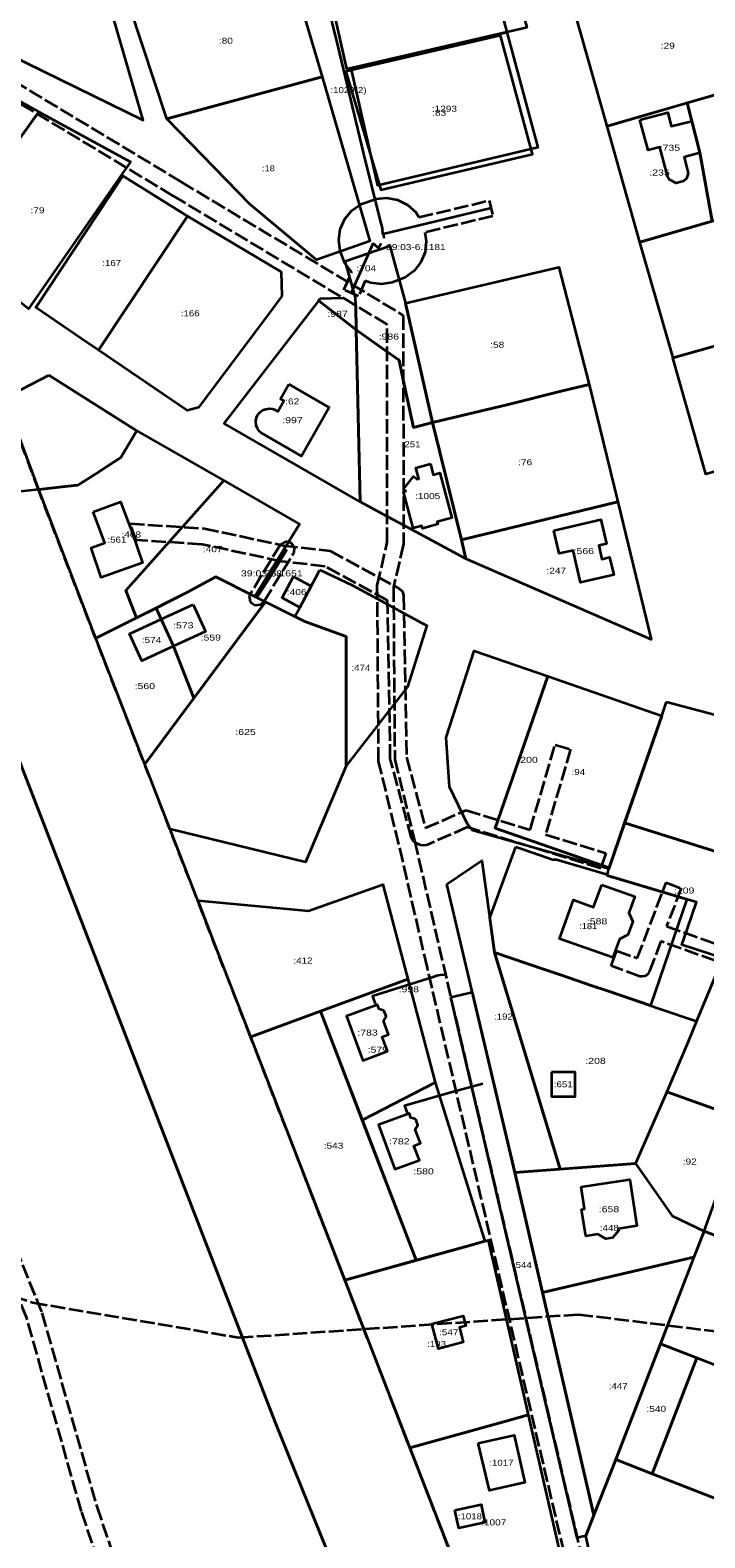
# Model space of a CAD drawing. Extents: x 1185507 to 1197690, y 352608 to 375774.
# Drawn here: x 1190232 to 1190399.7, y 364414.2 to 364788.9 of the extents above; entities that cross this region are included whole.
import ezdxf
from ezdxf.enums import TextEntityAlignment as Align

# ---------------------------------------------------------------- set-up
doc = ezdxf.new("R2010")
doc.units = 0
doc.header["$LTSCALE"] = 0.6
doc.linetypes.add('DOT_DASHED', pattern=[7.7, 5, -1.2, 0.3, -1.2])
doc.linetypes.add('LONG_DASHED', pattern=[7.5, 6, -1.5])
for name, color, linetype, lineweight in [('2', 7, 'Continuous', 35), ('4', 7, 'Continuous', 35), ('5', 7, 'DOT_DASHED', 35), ('7', 7, 'LONG_DASHED', 35), ('8', 7, 'Continuous', 35)]:
    doc.layers.add(name, color=color, linetype=linetype, lineweight=lineweight)

msp = doc.modelspace()

# ---------------------------------------------------------------- linework, layer by layer
at = {"layer": '2'}
for points in [[(1190203.76, 365183.45), (1190165.44, 365181.03), (1190143.28, 365179.63), (1190095.67, 365141.92), (1190101.13, 365121.7), (1190114.6, 365071.55), (1190134.43, 364996.3), (1190136.36, 364989.15), (1190143.36, 364963.22), (1190173.89, 364850.01), (1190182.86, 364818.75), (1190190.18, 364794.36), (1190194.07, 364783.25), (1190222.57, 364784.85), (1190260.08, 364766.56), (1190184.45, 365026.35), (1190319.42, 365061.39), (1190227.38, 365157.88), (1190211.55, 365175.02)], [(1190304.34, 364807.4), (1190340.66, 364817.71), (1190342.5, 364818.23), (1190346.35, 364819.32), (1190347.32, 364819.6), (1190355.39, 364789.56), (1190354.06, 364789.26), (1190350.41, 364788.44), (1190311.72, 364779.48), (1190310.66, 364779.27)], [(1190304.34, 364807.4), (1190340.66, 364817.71), (1190342.5, 364818.23), (1190350.41, 364788.44), (1190311.72, 364779.48), (1190310.66, 364779.27)], [(1190265.97, 364766.88), (1190256.67, 364795), (1190296.17, 364805.67), (1190304.54, 364777.29)], [(1190375.34, 364765.08), (1190367.16, 364793.94), (1190405.58, 364805.04), (1190413.76, 364776.18)], [(1190348.84, 364787.56), (1190310.41, 364778.62), (1190319.08, 364749.21), (1190356.85, 364758.13)], [(1190311.72, 364779.48), (1190350.41, 364788.44), (1190358.11, 364759.79), (1190318.39, 364750.33)], [(1190190.24, 364753.21), (1190203.97, 364774.43), (1190220.26, 364776.36), (1190234.11, 364768.65), (1190210.67, 364736.05)], [(1190304.54, 364777.29), (1190316.37, 364736.49), (1190303.16, 364731.87), (1190286.57, 364745.66), (1190265.97, 364766.88)], [(1190395.28, 364770.84), (1190413.76, 364776.18), (1190421.95, 364747.32), (1190401.46, 364741.41), (1190398.45, 364758.53), (1190396.46, 364766.26)], [(1190395.28, 364770.84), (1190396.46, 364766.26), (1190398.45, 364758.53), (1190401.46, 364741.41), (1190383.53, 364736.22), (1190375.34, 364765.08)], [(1190234.11, 364768.65), (1190256.91, 364756.16), (1190231.54, 364719.66), (1190210.67, 364736.05)], [(1190271.1, 364742.69), (1190248.97, 364709.35), (1190244.6, 364712.31), (1190233.35, 364719.98), (1190255, 364752.7)], [(1190383.53, 364736.22), (1190401.46, 364741.41), (1190421.95, 364747.32), (1190430.29, 364718.35), (1190391.8, 364707.51)], [(1190271.1, 364742.69), (1190294.32, 364728.84), (1190294.52, 364722.78), (1190291.19, 364718.3), (1190273.81, 364695.15), (1190270.98, 364694.41), (1190248.97, 364709.35)], [(1190310.23, 364731.53), (1190321.33, 364735.34), (1190325.25, 364721.06), (1190331.99, 364691.4), (1190327.24, 364690.18), (1190324.71, 364702), (1190323.65, 364706.9), (1190320.71, 364709), (1190313.03, 364714.47), (1190312.9, 364720.47), (1190312.86, 364722.42), (1190311.9, 364725.73)], [(1190325.25, 364721.06), (1190363.33, 364730.05), (1190370.87, 364700.85), (1190364.31, 364699.25), (1190350.45, 364695.77), (1190331.99, 364691.4)], [(1190303.94, 364722.22), (1190309.76, 364722.35), (1190312.91, 364720.46), (1190313.03, 364714.47), (1190303.71, 364721.65)], [(1190303.71, 364721.65), (1190313.03, 364714.47), (1190313.99, 364671.66), (1190280.21, 364691.14)], [(1190391.68, 364707.46), (1190430.17, 364718.37), (1190438.35, 364689.51), (1190399.87, 364678.6)], [(1190313.03, 364714.47), (1190320.71, 364709), (1190323.65, 364706.9), (1190324.71, 364702), (1190327.24, 364690.18), (1190331.99, 364691.4), (1190339.14, 364662.22), (1190340.28, 364657.54), (1190324.72, 364665.9), (1190320.73, 364668.05), (1190313.99, 364671.66)], [(1190236.59, 364703.15), (1190258.5, 364689.34), (1190258.18, 364688.84), (1190254.47, 364682.71), (1190251.22, 364680.53), (1190248.3, 364678.68), (1190243.78, 364675.8), (1190241.4, 364675.55), (1190234.09, 364674.74), (1190228.06, 364674.08), (1190209.26, 364671.93), (1190206.64, 364672.5), (1190201.63, 364685.08), (1190225.43, 364697.38)], [(1190331.99, 364691.4), (1190350.45, 364695.77), (1190364.31, 364699.25), (1190370.87, 364700.85), (1190378.01, 364671.67), (1190339.14, 364662.22)], [(1190258.5, 364689.34), (1190280.09, 364676.97), (1190255.71, 364649.69), (1190258.43, 364642.88), (1190248.28, 364637.8), (1190234.09, 364674.74), (1190241.4, 364675.55), (1190243.78, 364675.8), (1190248.3, 364678.68), (1190251.22, 364680.53), (1190254.47, 364682.71), (1190258.18, 364688.84)], [(1190280.09, 364676.97), (1190298.94, 364666.17), (1190287.79, 364648.2), (1190278.14, 364653.02), (1190271.06, 364649.2), (1190258.43, 364642.88), (1190255.71, 364649.69)], [(1190339.14, 364662.22), (1190378.01, 364671.67), (1190386.32, 364637.46), (1190340.28, 364657.54)], [(1190303.98, 364654.76), (1190311.98, 364650.96), (1190318.27, 364647.57), (1190329.43, 364641.54), (1190330.54, 364640.94), (1190325.74, 364625.72), (1190318.51, 364616.4), (1190316.61, 364613.95), (1190315.05, 364611.93), (1190310.53, 364606.11), (1190310.54, 364638.25), (1190300.27, 364641.96), (1190297.78, 364643.21), (1190298.98, 364645.44), (1190301.82, 364650.73), (1190302.87, 364652.68)], [(1190278.14, 364653.02), (1190287.79, 364648.2), (1190290.47, 364646.86), (1190272.64, 364622.9), (1190267.62, 364635.82), (1190263.24, 364645.29), (1190271.06, 364649.2)], [(1190297.41, 364653.09), (1190301.82, 364650.73), (1190298.98, 364645.44), (1190294.58, 364647.8)], [(1190263.24, 364645.29), (1190267.62, 364635.82), (1190272.64, 364622.9), (1190260.44, 364606.5), (1190248.28, 364637.8), (1190258.43, 364642.88)], [(1190290.47, 364646.86), (1190297.78, 364643.21), (1190300.27, 364641.96), (1190310.54, 364638.25), (1190310.53, 364606.11), (1190300.42, 364582.11), (1190266.72, 364590.33), (1190260.44, 364606.5)], [(1190375.86, 364580.73), (1190375.82, 364580.49), (1190342.01, 364590.01), (1190340.65, 364591.57), (1190336.19, 364600.82), (1190335.33, 364613.13), (1190342.36, 364634.63), (1190360.6, 364628.35), (1190347.5, 364590.56)], [(1190388.94, 364618.53), (1190375.86, 364580.73), (1190347.5, 364590.56), (1190360.6, 364628.35)], [(1190390.15, 364622), (1190419.82, 364614.11), (1190426.83, 364611.77), (1190415.6, 364585.92), (1190413.64, 364581.23), (1190379.72, 364591.89), (1190388.94, 364618.53)], [(1190379.72, 364591.89), (1190413.64, 364581.23), (1190405.75, 364562.26), (1190404.09, 364558.27), (1190393.92, 364561.55), (1190395.35, 364565.66), (1190397.61, 364572.21), (1190393.97, 364573.3), (1190390.13, 364574.45), (1190375.41, 364578.85), (1190375.82, 364580.49), (1190375.86, 364580.73)], [(1190352.65, 364585.97), (1190354.14, 364585.44), (1190358.69, 364583.91), (1190361.78, 364582.8), (1190362.76, 364582.82), (1190375.47, 364579.09), (1190375.41, 364578.85), (1190390.13, 364574.45), (1190393.97, 364573.3), (1190395.15, 364572.95), (1190386.12, 364546.51), (1190375.67, 364550.06), (1190371.41, 364551.51), (1190364.02, 364554.02), (1190359.81, 364555.45), (1190347.36, 364559.67), (1190346.18, 364568.32)], [(1190335.52, 364576.63), (1190344.23, 364582.55), (1190347.36, 364559.67), (1190363.66, 364505.83), (1190352.4, 364504.98)], [(1190273.68, 364572.61), (1190301.13, 364570), (1190319.64, 364576.62), (1190325.87, 364553.03), (1190304.11, 364545.06), (1190286.83, 364538.74), (1190278.06, 364561.35)], [(1190359.81, 364555.45), (1190364.02, 364554.02), (1190371.41, 364551.51), (1190375.67, 364550.06), (1190388.46, 364545.72), (1190397.62, 364542.61), (1190395.42, 364537.28), (1190390.17, 364525.06), (1190382.4, 364507.25), (1190363.66, 364505.83), (1190347.36, 364559.67)], [(1190403.12, 364555.96), (1190397.62, 364542.61), (1190395.42, 364537.28), (1190390.17, 364525.06), (1190409.42, 364518.15), (1190447.07, 364504.63), (1190463.54, 364498.72), (1190464.61, 364498.63), (1190474.33, 364527.61), (1190475.61, 364531.4), (1190458.61, 364536.92), (1190457.36, 364533.13), (1190449.18, 364508.39), (1190411.55, 364521.27), (1190420.58, 364549.92)], [(1190304.11, 364545.06), (1190325.87, 364553.03), (1190332.64, 364527.4), (1190314.51, 364518.02)], [(1190336.5, 364548.59), (1190341.83, 364549.82), (1190352.4, 364504.98), (1190359.29, 364475.21), (1190372.09, 364419.87), (1190370.06, 364414.67), (1190367.93, 364414.22)], [(1190286.83, 364538.74), (1190304.11, 364545.06), (1190327.89, 364483.19), (1190310.21, 364478.28)], [(1190314.51, 364518.02), (1190332.64, 364527.4), (1190343.92, 364491.34), (1190344.99, 364487.93), (1190341.26, 364486.9), (1190327.89, 364483.19), (1190326.64, 364486.46)], [(1190409.42, 364518.15), (1190390.17, 364525.06), (1190382.4, 364507.25), (1190391.55, 364494.27), (1190399.45, 364490.39)], [(1190409.42, 364518.15), (1190447.07, 364504.63), (1190436.76, 364475.93), (1190399.45, 364490.39)], [(1190352.4, 364504.98), (1190382.4, 364507.25), (1190391.55, 364494.27), (1190399.45, 364490.39), (1190396.95, 364483.93), (1190359.29, 364475.21)], [(1190436.76, 364475.93), (1190425.92, 364447.96), (1190388.63, 364462.41), (1190399.45, 364490.39)], [(1190310.21, 364478.28), (1190341.26, 364486.9), (1190345.8, 364488.16), (1190355.75, 364444.75), (1190351.41, 364443.54), (1190326.37, 364436.6), (1190316.54, 364461.96)], [(1190359.29, 364475.21), (1190396.95, 364483.93), (1190388.63, 364462.41), (1190377.5, 364433.71), (1190372.09, 364419.87)], [(1190388.63, 364462.41), (1190397.67, 364458.9), (1190386.53, 364430.1), (1190377.5, 364433.71)], [(1190397.68, 364458.91), (1190433.86, 364445.01), (1190422.7, 364416.02), (1190386.53, 364430.1)], [(1190326.37, 364436.6), (1190351.41, 364443.54), (1190355.75, 364444.75), (1190367.99, 364391.34), (1190343.8, 364391.63)], [(1190377.5, 364433.71), (1190386.53, 364430.1), (1190422.7, 364416.02), (1190412.2, 364396.54), (1190398.99, 364372.06), (1190382.22, 364376.24), (1190378.43, 364377.18), (1190370.06, 364414.67), (1190372.09, 364419.87)]]:
    msp.add_lwpolyline(points, close=True, dxfattribs=at)
msp.add_lwpolyline([(1190114.6, 365071.55), (1190134.43, 364996.3), (1190173.89, 364850.01), (1190182.86, 364818.75), (1190190.18, 364794.36), (1190199.57, 364767.56), (1190234, 364674.73), (1190248.22, 364637.78), (1190266.7, 364590.32), (1190286.74, 364538.7), (1190350.84, 364373.39), (1190352.99, 364368.35), (1190343.6, 364369.73), (1190322.42, 364366.99), (1190316.76, 364383.69), (1190292.82, 364442.97), (1190214.59, 364645.16), (1190183.58, 364726.16), (1190155.95, 364825.54), (1190120.01, 364961.77), (1190061.59, 365177.63)], dxfattribs=at)
at = {"layer": '4'}
msp.add_lwpolyline([(1190061.59, 365177.63), (1190120.01, 364961.77), (1190155.95, 364825.54), (1190183.58, 364726.16), (1190214.59, 364645.16), (1190292.82, 364442.97), (1190316.76, 364383.69), (1190322.42, 364366.99), (1190343.6, 364369.73), (1190404.66, 364360.8), (1190463.09, 364355.18), (1190532.29, 364357.36), (1190595.22, 364367.23), (1190611.29, 364369.51), (1190622.19, 364369.01), (1190626.4, 364363.08), (1190632.21, 364356.82), (1190647.14, 364349.43), (1190692.88, 364324.17)], dxfattribs=at)
at = {"layer": '5'}
msp.add_lwpolyline([(1190352.99, 364368.35), (1190350.84, 364373.39), (1190286.74, 364538.7), (1190266.7, 364590.32), (1190248.22, 364637.78), (1190234, 364674.73), (1190199.57, 364767.56), (1190190.18, 364794.36), (1190182.86, 364818.75), (1190173.89, 364850.01), (1190134.43, 364996.3), (1190114.6, 365071.55), (1190101.13, 365121.7), (1190038.78, 365352.65), (1190003.97, 365482.1), (1189962.17, 365637.31)], dxfattribs=at)
at = {"layer": '7'}
for points in [[(1190109.02, 365130.69), (1190159.16, 364944.69), (1190173.09, 364893.86), (1190200.95, 364792.55), (1190269.51, 364751.2), (1190324.7, 364718.04), (1190324.73, 364661.22), (1190322.25, 364650.44), (1190322.58, 364607.64), (1190327.51, 364587.48), (1190334.59, 364556.74), (1190377.79, 364372.08), (1190386.2, 364333.42), (1190391.64, 364310.22), (1190389.57, 364309.83), (1190390.12, 364307.36), (1190371.58, 364299.19), (1190342.02, 364287.5), (1190301.74, 364268.36), (1190295.27, 364266.24), (1190286.81, 364265.25), (1190139.2, 364244.98), (1189969.39, 364223.83)], [(1189968.83, 364227.79), (1190138.68, 364248.94), (1190286.31, 364269.22), (1190294.41, 364270.17), (1190300.26, 364272.09), (1190340.43, 364291.17), (1190370.04, 364302.88), (1190385.5, 364309.7), (1190384.77, 364312.99), (1190386.79, 364313.38), (1190382.3, 364332.53), (1190373.88, 364371.2), (1190330.69, 364555.84), (1190323.62, 364586.56), (1190318.58, 364607.14), (1190318.24, 364650.88), (1190320.73, 364661.67), (1190320.7, 364715.78), (1190267.44, 364747.77), (1190197.51, 364789.94), (1190169.23, 364892.8), (1190155.3, 364943.64), (1190105.15, 365129.71)], [(1190256.01, 364387.31), (1190244.7, 364420.77), (1190231.09, 364468.83), (1190192.51, 364563.99), (1190174.94, 364608.87), (1190156.56, 364649.95), (1190140.58, 364688.45), (1190123.12, 364729.39), (1190110.19, 364764.46), (1190097.53, 364801.35), (1190081.33, 364828.72), (1190049.35, 364881.85), (1190034.62, 364903.71), (1189979.33, 364977.11)], [(1189982.75, 364979.21), (1190037.95, 364905.94), (1190052.74, 364883.98), (1190084.77, 364830.77), (1190101.17, 364803.04), (1190114.01, 364765.67), (1190126.89, 364730.74), (1190144.27, 364690), (1190160.23, 364651.56), (1190178.62, 364610.46), (1190196.23, 364565.46), (1190234.88, 364470.1), (1190248.51, 364421.98), (1190259.88, 364388.36)], [(1189191.9, 364549.27), (1189395.22, 364588.56), (1189548.85, 364595.13), (1189680.04, 364579.91), (1189784.57, 364598.37), (1189872.95, 364591.01), (1190232.66, 364472.66), (1190283.77, 364463.98), (1190368.24, 364469.75), (1190452.8, 364459.37), (1190615.51, 364473.08), (1190678.91, 364456.96), (1190881.18, 364333.99), (1190940.56, 364356.34), (1190991.35, 364354.82), (1191177.32, 364502.05)], [(1190440.41, 364543.98), (1190388.71, 364562.46), (1190385.83, 364554.83), (1190385.39, 364554.22), (1190384.76, 364553.82), (1190384.11, 364553.68), (1190383.52, 364553.74), (1190376.38, 364556.39), (1190377.78, 364560.13), (1190382.85, 364558.25), (1190390.07, 364577.12), (1190393.78, 364575.65), (1190390.14, 364566.2), (1190447.76, 364545.74)]]:
    msp.add_lwpolyline(points, dxfattribs=at)
for points in [[(1190346.08, 364746.59), (1190347, 364742.69), (1190330.07, 364738.68), (1190330.43, 364736.5), (1190330.13, 364733.78), (1190329.1, 364731.25), (1190327.42, 364729.08), (1190325.21, 364727.46), (1190321.95, 364726.23), (1190319.25, 364725.79), (1190316.53, 364726.1), (1190315.24, 364726.62), (1190313.6, 364722.79), (1190309.94, 364724.41), (1190311.92, 364728.74), (1190310.21, 364731.01), (1190309.05, 364734.07), (1190308.68, 364736.78), (1190309.05, 364739.49), (1190310.14, 364742), (1190311.88, 364744.12), (1190314.12, 364745.69), (1190317.89, 364746.99), (1190320.61, 364747.23), (1190323.3, 364746.72), (1190325.75, 364745.5), (1190327.78, 364743.67), (1190328.58, 364742.4)], [(1190256.75, 364666.28), (1190275.22, 364665.09), (1190294.84, 364660.87), (1190306.54, 364659.53), (1190323.75, 364650.1), (1190324.48, 364649.42), (1190324.79, 364648.48), (1190325.48, 364608.24), (1190330.21, 364590.64), (1190340.37, 364595.08), (1190356.25, 364590.18), (1190362.44, 364611.33), (1190366.28, 364610.21), (1190360.07, 364589), (1190375.04, 364584.37), (1190373.8, 364580.57), (1190340.61, 364590.82), (1190330.47, 364586.38), (1190329.73, 364586.24), (1190328.99, 364586.38), (1190327.71, 364586.94), (1190327.13, 364587.41), (1190326.77, 364588.07), (1190321.48, 364607.83), (1190320.81, 364647.15), (1190305.3, 364655.65), (1190294.36, 364656.89), (1190274.69, 364661.11), (1190258.28, 364662.17)], [(1190295.47, 364661.82), (1190294.18, 364661.11), (1190286.37, 364648.31), (1190286.65, 364646.86), (1190287.84, 364645.99), (1190289.3, 364646.18), (1190290.03, 364646.86), (1190297.62, 364659.21), (1190297.69, 364660.21), (1190296.9, 364661.45)]]:
    msp.add_lwpolyline(points, close=True, dxfattribs=at)
at = {"layer": '8'}
msp.add_line((1190346.54, 364744.64), (1190319.68, 364738.24), dxfattribs=at)
for points in [[(1190302.65, 364808.66), (1190303.14, 364806.42), (1190308.47, 364784.83), (1190314.75, 364758.53), (1190319.02, 364741.19), (1190319.34, 364740), (1190319.51, 364739.39)], [(1190319.93, 364737.2), (1190319.86, 364738.07), (1190319.68, 364738.24), (1190319.62, 364738.5), (1190319.51, 364739.39)], [(1190319.24, 364735.88), (1190318.51, 364734.71), (1190317.59, 364735.56), (1190317.17, 364735.83), (1190311.77, 364723.6)], [(1190295.72, 364659.83), (1190292.83, 364655.04), (1190291.31, 364652.52), (1190288.34, 364647.93)], [(1190335.09, 364554.17), (1190333.91, 364554.02), (1190333.37, 364553.96), (1190333.04, 364553.91), (1190332.69, 364553.77), (1190332.11, 364553.56), (1190317.06, 364548.79), (1190317.68, 364546.93)], [(1190344.5, 364527.07), (1190335.96, 364524.68), (1190325.04, 364521.58), (1190325.68, 364519.85)]]:
    msp.add_lwpolyline(points, dxfattribs=at)
for points in [[(1190383.53, 364766.62), (1190390.46, 364768.47), (1190391.32, 364765.05), (1190396.44, 364766.33), (1190398.4, 364758.39), (1190394.48, 364757.35), (1190395.46, 364753.7), (1190395.5, 364753.33), (1190395.07, 364752.07), (1190394.37, 364751.35), (1190392.49, 364750.9), (1190390.78, 364751.78), (1190390.43, 364752.37), (1190388.49, 364759.86), (1190385.54, 364759.09)], [(1190296.24, 364700.92), (1190306.3, 364695.1), (1190299.38, 364683.06), (1190289.35, 364688.81), (1190288.96, 364689.17), (1190288.44, 364689.88), (1190288.12, 364690.7), (1190288.04, 364691.81), (1190288.22, 364692.63), (1190288.5, 364693.25), (1190288.82, 364693.68), (1190289.32, 364694.14), (1190289.89, 364694.53), (1190290.55, 364694.75), (1190291.47, 364694.88), (1190292.19, 364694.77), (1190292.65, 364694.63), (1190293.55, 364694.12), (1190295.04, 364696.75), (1190294.16, 364697.26)], [(1190331.44, 364681.13), (1190332.17, 364678.43), (1190333.77, 364678.86), (1190336.79, 364667.71), (1190333.13, 364666.73), (1190333.29, 364666.13), (1190329.47, 364665.1), (1190329.31, 364665.69), (1190327.18, 364665.12), (1190324.74, 364674.17), (1190325.33, 364674.33), (1190324.74, 364674.81), (1190327.28, 364678.01), (1190327.96, 364677.48), (1190328.09, 364677.3), (1190328.54, 364677.42), (1190327.8, 364680.15)], [(1190247.64, 364669.21), (1190254.42, 364671.71), (1190257.37, 364663.81), (1190259.92, 364656.51), (1190249.59, 364652.87), (1190247.11, 364660.26), (1190250.55, 364661.46)], [(1190362.13, 364664.53), (1190373.84, 364667.27), (1190375.25, 364661.25), (1190373.31, 364660.8), (1190374.08, 364657.47), (1190375.99, 364657.91), (1190377.01, 364653.56), (1190368.77, 364651.64), (1190366.91, 364659.61), (1190363.47, 364658.81)], [(1190272.44, 364646.15), (1190275.52, 364639.48), (1190267.62, 364635.82), (1190264.53, 364642.51)], [(1190264.53, 364642.51), (1190267.62, 364635.82), (1190259.72, 364632.16), (1190256.62, 364638.87)], [(1190374.09, 364576.46), (1190382.24, 364573.59), (1190380.77, 364569.58), (1190381.73, 364567.4), (1190380.5, 364564.04), (1190378.48, 364563), (1190376.76, 364558.41), (1190363.49, 364563.09), (1190367.03, 364572.75), (1190372, 364570.98)], [(1190319.87, 364545.25), (1190318.68, 364545.61), (1190318.29, 364546.67), (1190310.6, 364543.89), (1190314.65, 364532.86), (1190320.78, 364535.12), (1190319.43, 364538.69), (1190321.03, 364539.28), (1190319.77, 364542.68), (1190320.42, 364543.82)], [(1190361.52, 364529.96), (1190361.52, 364523.88), (1190367.41, 364523.88), (1190367.41, 364529.96)], [(1190327.79, 364518.23), (1190326.6, 364518.58), (1190326.21, 364519.65), (1190318.52, 364516.87), (1190322.57, 364505.83), (1190328.7, 364508.09), (1190327.35, 364511.67), (1190328.95, 364512.26), (1190327.69, 364515.66), (1190328.34, 364516.8)], [(1190368.93, 364501.4), (1190380.99, 364503.23), (1190382.73, 364491.71), (1190378.09, 364491), (1190378.16, 364490.54), (1190376.72, 364488.73), (1190375.03, 364488.52), (1190373.08, 364489.66), (1190370.11, 364489.22), (1190368.99, 364495.83), (1190369.75, 364495.96)], [(1190331.79, 364467.35), (1190339.55, 364469.41), (1190340.21, 364466.87), (1190338.64, 364466.46), (1190339.6, 364462.83), (1190333.42, 364461.19)], [(1190343.29, 364437.72), (1190352.23, 364439.76), (1190354.91, 364427.95), (1190346.14, 364425.96)], [(1190337.52, 364421.1), (1190344.03, 364422.5), (1190344.99, 364418.01), (1190338.48, 364416.61)]]:
    msp.add_lwpolyline(points, close=True, dxfattribs=at)

# ---------------------------------------------------------------- texts
at = {"layer": '2'}
for s, width, p in [(':80', 1.25, (1190280.6045, 364785.525)), (':29', 1.25, (1190390.4595, 364784.31)), (':1293', 1.25, (1190334.915, 364768.635)), (':83', 1.25, (1190333.6295, 364767.635)), (':18', 1.15, (1190291.17, 364753.83)), (':235', 1.3, (1190388.4005, 364752.78)), (':79', 1.25, (1190233.7895, 364743.405)), (':167', 1.2, (1190252.225, 364730.275)), (':166', 1.2, (1190271.745, 364717.8)), (':987', 1.3, (1190308.3705, 364717.66)), (':986', 1.3, (1190321.1105, 364712.01)), (':58', 1.25, (1190348.0595, 364709.975)), (':62', 1.25, (1190297.0995, 364695.905)), (':251', 1.2, (1190326.655, 364685.255)), (':76', 1.25, (1190354.9995, 364680.785)), (':408', 1.25, (1190257.0905, 364662.82)), (':407', 1.25, (1190277.3255, 364659.175)), (':247', 1.25, (1190362.7305, 364653.815)), (':406', 1.25, (1190298.2005, 364648.515)), (':559', 1.3, (1190276.8555, 364637.21)), (':474', 1.2, (1190314.16, 364629.685)), (':560', 1.3, (1190260.4605, 364625.145)), (':625', 1.3, (1190285.4905, 364613.735)), (':200', 1.3, (1190355.5955, 364606.81)), (':94', 1.2, (1190368.2195, 364603.79)), (':209', 1.3, (1190394.5255, 364574.33)), (':181', 1.15, (1190370.6645, 364565.49)), (':412', 1.2, (1190299.775, 364556.93)), (':192', 1.2, (1190349.59, 364543.015)), (':579', 1.3, (1190318.3755, 364534.775)), (':208', 1.3, (1190372.4905, 364532)), (':543', 1.25, (1190307.3605, 364510.92)), (':92', 1.25, (1190395.9095, 364506.975)), (':580', 1.3, (1190329.7505, 364504.545)), (':448', 1.2, (1190375.925, 364490.48)), (':544', 1.2, (1190354.295, 364481.27)), (':193', 1.2, (1190332.98, 364461.63)), (':447', 1.2, (1190378.12, 364451.15)), (':540', 1.25, (1190387.5855, 364445.505)), (':1007', 1.25, (1190347.18, 364417.295))]:
    msp.add_text(s, height=1.5, dxfattribs=dict(at, width=width)).set_placement(p, align=Align.CENTER)
at = {"layer": '7'}
for s, width, p in [('39:03-6.1181', 1.25, (1190327.84, 364734.26)), ('39:03-6.1651', 1.3, (1190292.03, 364653.155))]:
    msp.add_text(s, height=1.5, dxfattribs=dict(at, width=width)).set_placement(p, align=Align.CENTER)
at = {"layer": '8'}
for s, width, p in [(':1029(2)', 1.2, (1190311.0805, 364773.275)), (':735', 1.3, (1190390.9655, 364758.935)), (':704', 1.25, (1190315.5055, 364728.99)), (':997', 1.3, (1190297.1705, 364691.24)), (':1005', 1.25, (1190330.765, 364672.365)), (':561', 1.2, (1190253.515, 364661.54)), (':566', 1.3, (1190369.5705, 364658.705)), (':768', 1.3, (1190292.0305, 364653.13)), (':573', 1.3, (1190270.0255, 364640.235)), (':574', 1.25, (1190262.1205, 364636.585)), (':588', 1.3, (1190372.8655, 364566.685)), (':998', 1.3, (1190326.0755, 364549.8)), (':783', 1.3, (1190315.8155, 364539.015)), (':651', 1.2, (1190364.465, 364526.17)), (':782', 1.3, (1190323.7355, 364511.99)), (':658', 1.3, (1190375.8305, 364495.125)), (':547', 1.25, (1190336.0005, 364464.55)), (':1017', 1.2, (1190349.1005, 364432.11)), (':1018', 1.2, (1190341.2555, 364418.805))]:
    msp.add_text(s, height=1.5, dxfattribs=dict(at, width=width)).set_placement(p, align=Align.CENTER)

doc.saveas('drawing.dxf')
